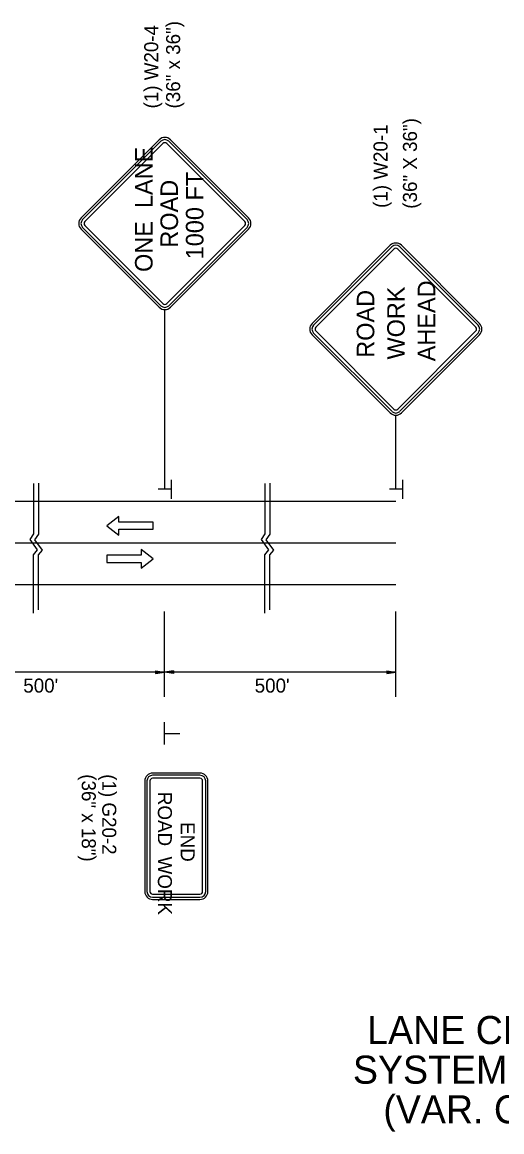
# Model space of a CAD drawing. Extents: x 1925873 to 1930787, y 596452 to 599617.
# Drawn here: x 1928221.2 to 1928426.2, y 596693.5 to 597167.6 of the extents above; entities that cross this region are included whole.
import ezdxf

# ---------------------------------------------------------------- set-up
doc = ezdxf.new("R2010")
doc.units = 0
for name, color, linetype in [('Default', 7, 'Continuous'), ('P_TC_Signs_Temporary', 7, 'Continuous'), ('R_Border', 7, 'Continuous'), ('R_Striping', 7, 'Continuous')]:
    doc.layers.add(name, color=color, linetype=linetype)

msp = doc.modelspace()

# ---------------------------------------------------------------- linework, layer by layer
at = {"layer": 'Default'}
for p, q in [((1928284.85, 596971.99), (1928284.85, 596963.98)), ((1928383.75, 596971.99), (1928383.75, 596963.98)), ((1928284.73, 596968.01), (1928279.27, 596968.01)), ((1928383.63, 596968.01), (1928378.17, 596968.01)), ((1927951.04, 596962.91), (1928380.9, 596962.88)), ((1927951.04, 596945.12), (1928380.9, 596945.09)), ((1927951.04, 596927.33), (1928380.9, 596927.3)), ((1928282, 596879.27), (1928282, 596915.85)), ((1928380.9, 596879.27), (1928380.9, 596915.85)), ((1928282, 596889.86), (1928182.25, 596889.86)), ((1928278.16, 596890.43), (1928282, 596889.86)), ((1928278.16, 596890.43), (1928278.16, 596889.28)), ((1928278.16, 596890.34), (1928281.36, 596889.86)), ((1928278.16, 596890.24), (1928280.7, 596889.86)), ((1928278.16, 596890.14), (1928280.06, 596889.86)), ((1928278.16, 596890.04), (1928279.41, 596889.86)), ((1928278.16, 596889.95), (1928278.77, 596889.86)), ((1928278.16, 596889.28), (1928282, 596889.86)), ((1928278.16, 596889.67), (1928279.41, 596889.86)), ((1928278.16, 596889.48), (1928280.7, 596889.86)), ((1928278.16, 596889.38), (1928281.36, 596889.86)), ((1928278.16, 596889.57), (1928280.06, 596889.86)), ((1928278.16, 596889.77), (1928278.77, 596889.86)), ((1928380.9, 596889.86), (1928281.15, 596889.86)), ((1928285.85, 596890.43), (1928282.02, 596889.86)), ((1928285.85, 596889.28), (1928282.02, 596889.86)), ((1928285.85, 596890.34), (1928282.66, 596889.86)), ((1928285.85, 596889.38), (1928282.66, 596889.86)), ((1928285.85, 596890.24), (1928283.32, 596889.86)), ((1928285.85, 596889.48), (1928283.32, 596889.86)), ((1928285.85, 596890.14), (1928283.96, 596889.86)), ((1928285.85, 596889.57), (1928283.96, 596889.86)), ((1928285.85, 596890.04), (1928284.61, 596889.86)), ((1928285.85, 596889.67), (1928284.61, 596889.86)), ((1928285.85, 596889.95), (1928285.25, 596889.86)), ((1928285.85, 596889.77), (1928285.25, 596889.86)), ((1928285.85, 596890.43), (1928285.85, 596889.28)), ((1928377.06, 596890.43), (1928380.9, 596889.86)), ((1928377.06, 596890.43), (1928377.06, 596889.28)), ((1928377.06, 596890.34), (1928380.26, 596889.86)), ((1928377.06, 596890.24), (1928379.6, 596889.86)), ((1928377.06, 596890.14), (1928378.96, 596889.86)), ((1928377.06, 596890.04), (1928378.31, 596889.86)), ((1928377.06, 596889.95), (1928377.67, 596889.86)), ((1928377.06, 596889.28), (1928380.9, 596889.86)), ((1928377.06, 596889.67), (1928378.31, 596889.86)), ((1928377.06, 596889.48), (1928379.6, 596889.86)), ((1928377.06, 596889.38), (1928380.26, 596889.86)), ((1928377.06, 596889.57), (1928378.96, 596889.86)), ((1928377.06, 596889.77), (1928377.67, 596889.86)), ((1928282, 596858.95), (1928282, 596868.44)), ((1928282.14, 596863.67), (1928288.62, 596863.67))]:
    msp.add_line(p, q, dxfattribs=at)
for points in [[(1928226.07, 596970.49), (1928226.07, 596948.97), (1928224.41, 596946.5), (1928227.65, 596942.07), (1928225.94, 596940.02), (1928225.94, 596915)], [(1928228.12, 596970.69), (1928228.12, 596948.88), (1928226.46, 596946.41), (1928229.69, 596941.98), (1928227.99, 596939.94), (1928227.98, 596916.44)], [(1928324.97, 596970.49), (1928324.97, 596948.97), (1928323.31, 596946.5), (1928326.55, 596942.07), (1928324.84, 596940.02), (1928324.84, 596915)], [(1928327.02, 596970.69), (1928327.02, 596948.88), (1928325.36, 596946.41), (1928328.59, 596941.98), (1928326.89, 596939.94), (1928326.89, 596916.44)]]:
    msp.add_lwpolyline(points, dxfattribs=at)
at = {"layer": 'P_TC_Signs_Temporary'}
for p, q in [((1928246.38, 597083.95), (1928279.79, 597117.36)), ((1928247.04, 597083.29), (1928280.45, 597116.7)), ((1928283.9, 597116.7), (1928317.31, 597083.29)), ((1928284.56, 597117.36), (1928317.97, 597083.95)), ((1928247.97, 597082.36), (1928281.38, 597115.77)), ((1928282.97, 597115.77), (1928316.38, 597082.36)), ((1928279.79, 597045.77), (1928246.38, 597079.18)), ((1928280.45, 597046.43), (1928247.04, 597079.84)), ((1928281.38, 597047.36), (1928247.97, 597080.77)), ((1928316.38, 597080.77), (1928282.97, 597047.36)), ((1928317.31, 597079.84), (1928283.9, 597046.43)), ((1928317.97, 597079.18), (1928284.56, 597045.77)), ((1928345.11, 597038.84), (1928378.52, 597072.25)), ((1928345.77, 597038.18), (1928379.18, 597071.59)), ((1928346.7, 597037.25), (1928380.11, 597070.66)), ((1928381.7, 597070.66), (1928415.11, 597037.25)), ((1928382.63, 597071.59), (1928416.04, 597038.18)), ((1928383.29, 597072.25), (1928416.7, 597038.84)), ((1928380.11, 597002.25), (1928346.7, 597035.66)), ((1928415.11, 597035.66), (1928381.7, 597002.25)), ((1928378.52, 597000.66), (1928345.11, 597034.07)), ((1928379.18, 597001.32), (1928345.77, 597034.73)), ((1928416.04, 597034.73), (1928382.63, 597001.32)), ((1928416.7, 597034.07), (1928383.29, 597000.66)), ((1928297.2, 596846.75), (1928276.95, 596846.75)), ((1928297.2, 596845.82), (1928276.95, 596845.82)), ((1928273.57, 596843.38), (1928273.57, 596796.13)), ((1928274.51, 596843.38), (1928274.51, 596796.13)), ((1928275.82, 596843.38), (1928275.82, 596796.13)), ((1928297.2, 596844.5), (1928276.95, 596844.5)), ((1928298.32, 596796.13), (1928298.32, 596843.38)), ((1928299.63, 596796.13), (1928299.63, 596843.38)), ((1928300.57, 596796.13), (1928300.57, 596843.38)), ((1928276.95, 596795), (1928297.2, 596795)), ((1928276.95, 596793.69), (1928297.2, 596793.69)), ((1928276.95, 596792.75), (1928297.2, 596792.75))]:
    msp.add_line(p, q, dxfattribs=at)
for centre, radius, start, end in [((1928282.18, 597114.98), 3.38, 45, 135), ((1928282.18, 597114.98), 2.44, 45, 135), ((1928282.18, 597114.98), 1.13, 45, 135), ((1928248.76, 597081.57), 3.38, 135, 225), ((1928248.76, 597081.57), 2.44, 135, 225), ((1928315.59, 597081.57), 2.44, 315, 45), ((1928315.59, 597081.57), 3.38, 315, 45), ((1928248.76, 597081.57), 1.13, 135, 225), ((1928315.59, 597081.57), 1.13, 315, 45), ((1928380.9, 597069.86), 3.38, 45, 135), ((1928380.9, 597069.86), 2.44, 45, 135), ((1928380.9, 597069.86), 1.13, 45, 135), ((1928282.18, 597048.16), 3.38, 225, 315), ((1928282.18, 597048.16), 2.44, 225, 315), ((1928282.18, 597048.16), 1.13, 225, 315), ((1928347.49, 597036.45), 3.38, 135, 225), ((1928347.49, 597036.45), 2.44, 135, 225), ((1928347.49, 597036.45), 1.13, 135, 225), ((1928414.31, 597036.45), 1.13, 315, 45), ((1928414.31, 597036.45), 2.44, 315, 45), ((1928414.31, 597036.45), 3.38, 315, 45), ((1928380.9, 597003.04), 3.38, 225, 315), ((1928380.9, 597003.04), 2.44, 225, 315), ((1928380.9, 597003.04), 1.13, 225, 315), ((1928276.95, 596843.38), 3.37, 90, 180), ((1928276.95, 596843.38), 2.44, 90, 180), ((1928297.2, 596843.38), 3.37, 360, 90), ((1928297.2, 596843.38), 2.44, 360, 90), ((1928276.95, 596843.38), 1.13, 90, 180), ((1928297.2, 596843.38), 1.13, 360, 90), ((1928276.95, 596796.13), 3.37, 180, 270), ((1928276.95, 596796.13), 2.44, 180, 270), ((1928276.95, 596796.13), 1.13, 180, 270), ((1928297.2, 596796.13), 2.44, 270, 360), ((1928297.2, 596796.13), 1.13, 270, 360), ((1928297.2, 596796.13), 3.37, 270, 360)]:
    msp.add_arc(centre, radius, start, end, dxfattribs=at)
at = {"layer": 'R_Border'}
for p, q in [((1928282.18, 596968.01), (1928282.18, 597044.78)), ((1928380.9, 596968.01), (1928380.9, 596999.67))]:
    msp.add_line(p, q, dxfattribs=at)
at = {"layer": 'R_Striping'}
for points in [[(1928262.51, 596956.42), (1928257.32, 596952.42), (1928262.51, 596948.42), (1928262.51, 596950.92), (1928277.23, 596950.92), (1928277.23, 596953.92), (1928262.51, 596953.92)], [(1928272.03, 596934.29), (1928277.23, 596938.29), (1928272.03, 596942.29), (1928272.03, 596939.79), (1928257.32, 596939.79), (1928257.32, 596936.79), (1928272.03, 596936.79)]]:
    msp.add_lwpolyline(points, close=True, dxfattribs=at)

# ---------------------------------------------------------------- texts
at = {"layer": 'Default'}
for s, height, rotation, p in [('(36" X 36")', 6, 90, (1928389.94, 597087.9)), ('(1) W20-1', 6, 90, (1928377.37, 597088.24)), ("500'", 6, 359.9922, (1928221.68, 596881.13)), ("500'", 6, 359.9922, (1928320.58, 596881.13)), ('LANE CLOSURE WITH PORTABLE TRAFFIC SIGNAL ', 12, 360, (1928368.66, 596730.95)), ('SYSTEM & TRAFFIC DRUMS FOR HYDRODEMOLITION', 12, 360, (1928362.57, 596714.01)), ('(VAR. CLEAR ROADWAY ON THE BRIDGE DECKS)', 12, 360, (1928375.56, 596697.06))]:
    msp.add_text(s, height=height, rotation=rotation, dxfattribs=at).set_placement(p)
at = {"layer": 'P_TC_Signs_Temporary'}
for s, height, rotation, p in [('ONE  LANE', 7.5, 90, (1928276.93, 597060.87)), ('1000 FT', 7.5, 90, (1928298.68, 597066.28)), ('ROAD', 7.5, 90, (1928287.8, 597071.26)), ('WORK', 7.5, 90, (1928384.71, 597023.46)), (' AHEAD ', 7.5, 90, (1928397.74, 597019.91)), (' ROAD ', 7.5, 90, (1928371.69, 597021.43)), ('ROAD  WORK', 6, 270, (1928279.2, 596838.71)), ('END', 6, 270, (1928288.95, 596825.78))]:
    msp.add_text(s, height=height, rotation=rotation, dxfattribs=at).set_placement(p)
at = {"layer": 'R_Border'}
for s, height, rotation, p in [('(1) W20-4', 6, 90, (1928279.35, 597130.74)), ('(36" x 36")', 5.9996, 90, (1928288.71, 597130.74)), ('(36" x 18")', 5.9996, 270, (1928246.67, 596846.24)), ('(1) G20-2', 6, 270, (1928255.42, 596846.24))]:
    msp.add_text(s, height=height, rotation=rotation, dxfattribs=at).set_placement(p)

doc.saveas('drawing.dxf')
